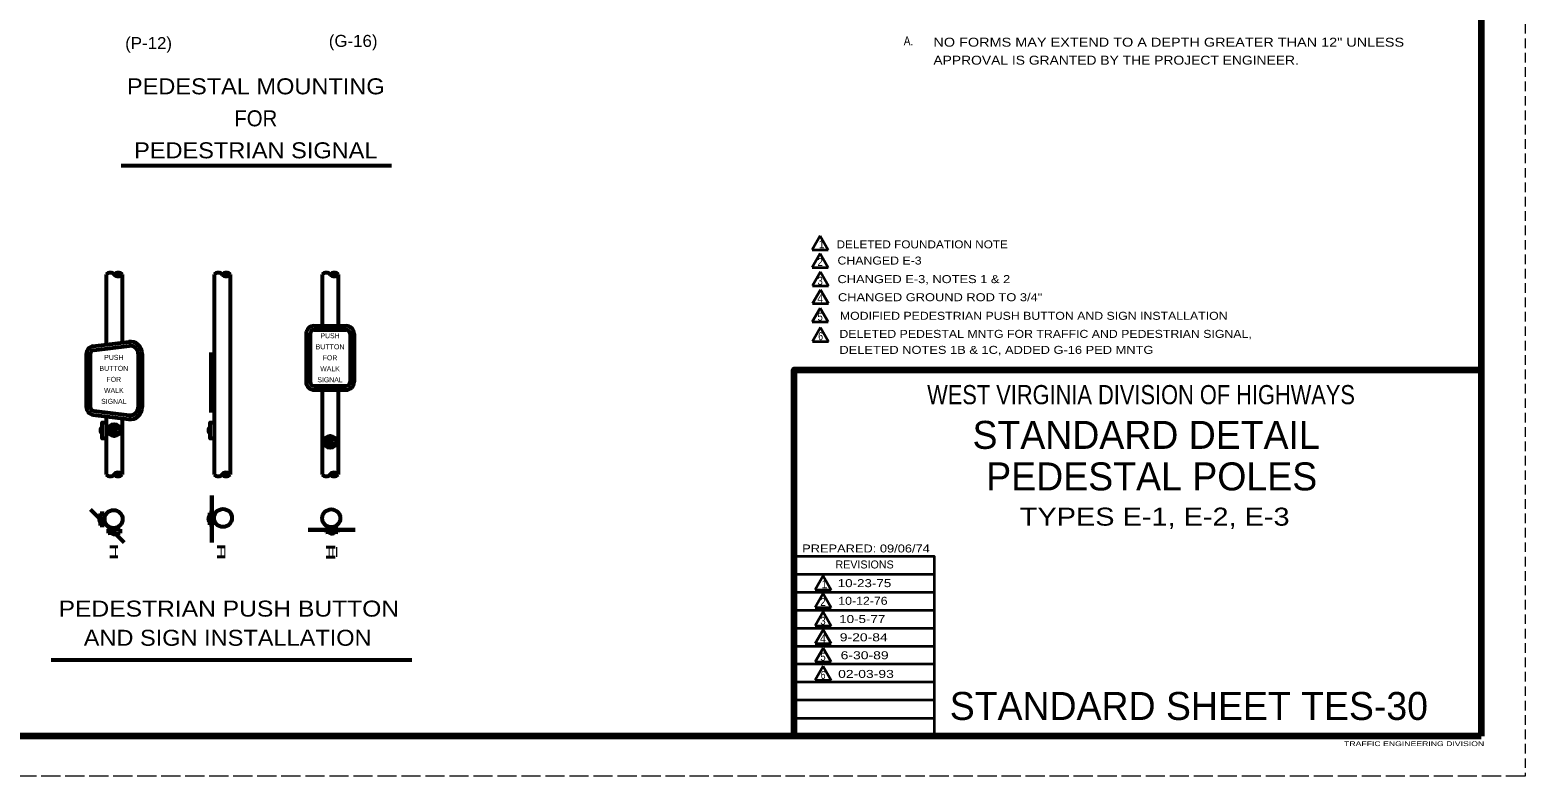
# Model space of a CAD drawing. Extents: x -608 to 72, y 36 to 476.
# Drawn here: x -301.5 to 72.2, y 35.6 to 222.1 of the extents above; entities that cross this region are included whole.
import ezdxf
from ezdxf.enums import TextEntityAlignment as Align

# ---------------------------------------------------------------- set-up
doc = ezdxf.new("R2010")
doc.units = 0
doc.header["$LTSCALE"] = 0.8
doc.linetypes.add('LONG_DASHED', pattern=[7.5, 6, -1.5])
doc.linetypes.add('MEDIUM_DASHED', pattern=[4.5, 3, -1.5])
doc.layers.add('1', color=7, linetype='Continuous', lineweight=53)
doc.layers.add('61', color=7, linetype='Continuous', lineweight=35)

msp = doc.modelspace()

# ---------------------------------------------------------------- linework, layer by layer
at = {"layer": '1', "linetype": 'MEDIUM_DASHED', "lineweight": 13}
msp.add_line((72.1969, 475.5947), (72.1769, 35.5747), dxfattribs=at)
at = {"layer": '1'}
for p, q in [((-278.6894, 188.1896), (-211.1222, 188.1896)), ((-282.3844, 160.9454), (-282.3844, 143.4454)), ((-278.3844, 160.9454), (-278.3844, 143.9454)), ((-251.3844, 160.9454), (-251.3844, 143.9454)), ((-228.3844, 160.9454), (-228.3844, 148.1722)), ((-224.3844, 160.9454), (-224.3844, 148.1192)), ((-232.4268, 146.1192), (-232.4268, 134.1192)), ((-231.4268, 146.1192), (-231.4268, 134.1192)), ((-230.4268, 148.1192), (-222.4268, 148.1192)), ((-230.4268, 147.1192), (-222.4268, 147.1192)), ((-221.4268, 146.1192), (-221.4268, 134.1192)), ((-220.4268, 146.1192), (-220.4268, 134.1192)), ((-285.6325, 143.0394), (-276.7565, 144.1489)), ((-285.5084, 142.0472), (-276.6325, 143.1567)), ((-251.3844, 143.9454), (-251.3844, 110.9958)), ((-287.3844, 141.0548), (-287.3844, 127.8864)), ((-286.3844, 141.0549), (-286.3844, 127.8863)), ((-274.3844, 141.1721), (-274.3844, 127.7692)), ((-273.3844, 141.1721), (-273.3844, 127.7692)), ((-256.1344, 126.4958), (-256.1344, 141.4958)), ((-256.1344, 139.0958), (-255.3844, 139.0958)), ((-256.1344, 137.9958), (-255.3844, 137.9958)), ((-230.4268, 133.1192), (-222.4268, 133.1192)), ((-230.4268, 132.1192), (-222.4268, 132.1192)), ((-228.3844, 132.1192), (-228.3844, 110.9958)), ((-224.3844, 132.1192), (-224.3844, 110.9958)), ((-256.1344, 129.9958), (-255.3844, 129.9958)), ((-256.1344, 128.8958), (-255.3844, 128.8958)), ((-285.6325, 125.9018), (-276.7565, 124.7923)), ((-285.5084, 126.8941), (-276.6325, 125.7846)), ((-282.3844, 125.4958), (-282.3844, 110.9958)), ((-278.3844, 124.9958), (-278.3844, 110.9958)), ((-282.8841, 101.2534), (-283.8841, 101.2534)), ((-255.597, 101.3492), (-256.597, 101.3492)), ((-282.8841, 98.2534), (-283.8841, 98.2534)), ((-282.7841, 99.7534), (-283.7841, 99.7534)), ((-281.8974, 97.3155), (-281.8974, 96.3155)), ((-280.3974, 97.4156), (-280.3974, 96.4155)), ((-278.8974, 97.3155), (-278.8974, 96.3155)), ((-255.597, 98.3492), (-256.597, 98.3492)), ((-255.497, 99.8492), (-256.497, 99.8492)), ((-227.5146, 97.507), (-227.5146, 96.507)), ((-226.0146, 97.6071), (-226.0146, 96.607)), ((-224.5146, 97.507), (-224.5146, 96.507)), ((-296.1583, 64.6672), (-205.9782, 64.6672))]:
    msp.add_line(p, q, dxfattribs=at)
at = {"layer": '1', "lineweight": 35}
for p, q in [((-103.9602, 170.6178), (-105.9602, 167.1537)), ((-103.9602, 170.6178), (-101.9602, 167.1537)), ((-105.9602, 167.1537), (-101.9602, 167.1537)), ((-103.9602, 166.2022), (-105.9602, 162.7382)), ((-103.9602, 166.2022), (-101.9602, 162.7382)), ((-105.9602, 162.7382), (-101.9602, 162.7382)), ((-103.8866, 161.6396), (-105.8866, 158.1755)), ((-103.8866, 161.6396), (-101.8866, 158.1755)), ((-105.8866, 158.1755), (-101.8866, 158.1755)), ((-103.8866, 157.1505), (-105.8866, 153.6864)), ((-103.8866, 157.1505), (-101.8866, 153.6864)), ((-105.8866, 153.6864), (-101.8866, 153.6864)), ((-103.9602, 152.5877), (-105.9602, 149.1237)), ((-103.9602, 152.5877), (-101.9602, 149.1237)), ((-105.9602, 149.1237), (-101.9602, 149.1237)), ((-103.8497, 147.724), (-105.8497, 144.2599)), ((-103.8497, 147.724), (-101.8497, 144.2599)), ((-105.8497, 144.2599), (-101.8497, 144.2599)), ((-75.4231, 85.9947), (-110.4031, 85.9947)), ((-103.2573, 85.6079), (-105.2573, 82.1438)), ((-103.2573, 85.6079), (-101.2573, 82.1438)), ((-75.4231, 81.4947), (-110.4031, 81.4947)), ((-105.2573, 82.1438), (-101.2573, 82.1438)), ((-103.2573, 81.1924), (-105.2573, 77.7283)), ((-103.2573, 81.1924), (-101.2573, 77.7283)), ((-75.4231, 76.9947), (-110.4031, 76.9947)), ((-105.2573, 77.7283), (-101.2573, 77.7283)), ((-103.1838, 76.6298), (-105.1838, 73.1657)), ((-103.1838, 76.6298), (-101.1838, 73.1657)), ((-75.4231, 72.4747), (-110.4031, 72.4747)), ((-105.1838, 73.1657), (-101.1838, 73.1657)), ((-103.1838, 72.1407), (-105.1838, 68.6766)), ((-103.1838, 72.1407), (-101.1838, 68.6766)), ((-75.4231, 67.9947), (-110.4031, 67.9947)), ((-103.2573, 67.5779), (-105.2573, 64.1138)), ((-105.1838, 68.6766), (-101.1838, 68.6766)), ((-103.2573, 67.5779), (-101.2573, 64.1138)), ((-105.2573, 64.1138), (-101.2573, 64.1138)), ((-75.4231, 63.5147), (-110.4031, 63.5147)), ((-103.2239, 63.0232), (-105.2239, 59.5591)), ((-103.2239, 63.0232), (-101.2239, 59.5591)), ((-75.4231, 59.0147), (-110.4031, 59.0147)), ((-105.2239, 59.5591), (-101.2239, 59.5591)), ((-75.4231, 54.5147), (-110.4031, 54.5147)), ((-75.4231, 49.9947), (-110.4031, 49.9947))]:
    msp.add_line(p, q, dxfattribs=at)
at = {"layer": '1', "lineweight": 60}
for p, q in [((-255.9803, 105.7435), (-255.9803, 93.9646)), ((-286.2768, 102.2103), (-277.9047, 93.9587)), ((-231.9415, 97.1089), (-220.1626, 97.1088))]:
    msp.add_line(p, q, dxfattribs=at)
at = {"layer": '1', "lineweight": 40}
for p, q in [((-281.4969, 92.8757), (-279.4969, 92.8757)), ((-281.4969, 90.3757), (-279.4969, 90.3757)), ((-254.6945, 92.8569), (-252.6945, 92.8569)), ((-254.6945, 90.3569), (-252.6945, 90.3569)), ((-227.3913, 92.81), (-225.1913, 92.81)), ((-227.3913, 90.31), (-225.1913, 90.31))]:
    msp.add_line(p, q, dxfattribs=at)
at = {"layer": '1'}
for points in [[(-255.3844, 160.9454), (-255.3844, 143.4454), (-255.3844, 110.9958)], [(-282.3844, 119.9958), (-283.3844, 119.9958), (-283.3844, 123.9958), (-282.3844, 123.9958)], [(-255.3844, 119.9958), (-256.3844, 119.9958), (-256.3844, 123.9958), (-255.3844, 123.9958)], [(-283.8841, 101.2534), (-283.7841, 99.7534), (-283.8841, 98.2534)], [(-282.8841, 101.2534), (-282.7841, 99.7534), (-282.8841, 98.2534)], [(-256.597, 101.3492), (-256.497, 99.8492), (-256.597, 98.3492)], [(-255.597, 101.3492), (-255.497, 99.8492), (-255.597, 98.3492)], [(-281.8974, 97.3155), (-280.3974, 97.4156), (-278.8974, 97.3155)], [(-227.5146, 97.507), (-226.0146, 97.6071), (-224.5146, 97.507)], [(-281.8974, 96.3155), (-280.3974, 96.4155), (-278.8974, 96.3155)], [(-227.5146, 96.507), (-226.0146, 96.607), (-224.5146, 96.507)]]:
    msp.add_lwpolyline(points, dxfattribs=at)
at = {"layer": '1', "lineweight": 158}
msp.add_lwpolyline([(-110.4231, 45.5547), (-110.4231, 137.1347), (61.2369, 137.1347)], dxfattribs=at)
at = {"layer": '1', "lineweight": 35}
msp.add_lwpolyline([(-75.4231, 45.5147), (-75.4231, 90.4747), (-110.4031, 90.4747)], dxfattribs=at)
at = {"layer": '1'}
for centre, radius in [((-280.3915, 122.0646), 1.5), ((-280.3915, 122.0646), 0.75), ((-280.3915, 122.0646), 0.25), ((-280.3997, 122.0652), 0.2098), ((-280.4063, 122.0685), 0.164), ((-280.4096, 122.0685), 0.1278), ((-280.4128, 122.0751), 0.0917), ((-280.4194, 122.0816), 0.0528), ((-280.4194, 122.0817), 0.0197), ((-226.4268, 119.1192), 1.5), ((-226.4268, 119.1192), 0.75), ((-226.4268, 119.1192), 0.25), ((-226.4351, 119.1199), 0.2098), ((-226.4417, 119.1232), 0.164), ((-226.445, 119.1232), 0.1278), ((-226.4482, 119.1298), 0.0917), ((-226.4547, 119.1363), 0.0528), ((-226.4547, 119.1363), 0.0197), ((-280.5435, 99.8226), 2.25), ((-253.2081, 100.0978), 2.25), ((-226.1607, 100.0141), 2.25)]:
    msp.add_circle(centre, radius, dxfattribs=at)
for centre, radius, start, end in [((-281.3844, 160.0295), 1.3561, 42.48748, 137.51252), ((-279.4041, 161.8953), 1.3561, 222.48748, 317.51252), ((-279.3951, 160.0458), 1.3561, 42.48748, 137.51252), ((-254.3844, 160.0295), 1.3561, 42.48748, 137.51252), ((-252.4041, 161.8953), 1.3561, 222.48748, 317.51252), ((-252.3951, 160.0458), 1.3561, 42.48748, 137.51252), ((-227.3844, 160.0295), 1.3561, 42.48748, 137.51252), ((-225.4041, 161.8953), 1.3561, 222.48748, 317.51252), ((-225.3951, 160.0458), 1.3561, 42.48748, 137.51252), ((-230.4268, 146.1192), 2, 90, 180), ((-230.4268, 146.1192), 1, 90, 180), ((-222.4268, 146.1192), 2, 0, 90), ((-222.4268, 146.1192), 1, 0, 90), ((-285.3844, 141.0549), 2, 97.12478, 180), ((-285.3844, 141.0549), 1, 97.12502, 180), ((-276.3844, 141.1721), 3, 0, 97.12484), ((-276.3844, 141.1721), 2, 0, 97.12508), ((-230.4268, 134.1192), 2, 180, 270), ((-230.4268, 134.1192), 1, 180, 270), ((-222.4268, 134.1192), 2, 270, 0), ((-222.4268, 134.1192), 1, 270, 0), ((-285.3844, 127.8864), 2, 180, 262.87522), ((-285.3844, 127.8864), 1, 180, 262.87498), ((-276.3844, 127.7692), 3, 262.87516, 0), ((-276.3844, 127.7691), 2, 262.87492, 0), ((-282.9459, 121.9958), 0.8688, 120.31709, 239.68291), ((-255.9459, 121.9958), 0.8688, 120.31709, 239.68291), ((-281.3844, 111.9118), 1.3561, 222.48748, 317.51252), ((-279.4419, 111.8768), 1.3561, 222.48748, 317.51252), ((-279.4228, 110.0833), 1.3561, 42.48748, 137.51252), ((-254.3844, 111.9118), 1.3561, 222.48748, 317.51252), ((-252.4419, 111.8768), 1.3561, 222.48748, 317.51252), ((-252.4228, 110.0833), 1.3561, 42.48748, 137.51252), ((-227.3844, 111.9118), 1.3561, 222.48748, 317.51252), ((-225.4419, 111.8768), 1.3561, 222.48748, 317.51252), ((-225.4228, 110.0833), 1.3561, 42.48748, 137.51252), ((-283.1525, 99.7534), 1.0134, 132.26342, 227.73658), ((-255.8654, 99.8492), 1.0134, 132.26342, 227.73658), ((-280.3974, 97.0471), 1.0134, 222.26342, 317.73658), ((-226.0146, 97.2386), 1.0134, 222.26342, 317.73658)]:
    msp.add_arc(centre, radius, start, end, dxfattribs=at)
at = {"layer": '61', "lineweight": 158}
for p, q in [((61.2169, 465.5947), (61.2369, 45.5547)), ((61.2369, 45.5547), (-577.8231, 45.5747))]:
    msp.add_line(p, q, dxfattribs=at)
at = {"layer": '61', "linetype": 'LONG_DASHED', "lineweight": 13}
msp.add_line((72.1769, 35.5747), (-607.8831, 35.5547), dxfattribs=at)

# ---------------------------------------------------------------- texts
at = {"layer": '1'}
for s, height, width, p in [('(P-12)', 3, 1.05, (-271.798, 217.3239)), ('(G-16)', 3, 1.05, (-220.6732, 217.8786)), ('PEDESTAL MOUNTING', 4, 1.1, (-245.0061, 206.0188)), ('FOR', 4, 0.95, (-245.0061, 198.0188)), ('PEDESTRIAN SIGNAL', 4, 1.1, (-245.0061, 190.0188)), ('2', 2, 0.9, (-103.9639, 163.1012)), ('3', 2, 0.9, (-103.9639, 158.3912)), ('4', 2, 0.95, (-103.9639, 153.9758)), ('5', 2, 0.9, (-103.9639, 149.4131)), ('6', 2, 0.8, (-103.8534, 144.5493)), ('BUTTON', 1.25, 1.05, (-226.4549, 142.2732)), ('FOR', 1.25, 0.95, (-226.4549, 139.5232)), ('BUTTON', 1.25, 1.05, (-280.4884, 136.8779)), ('FOR', 1.25, 0.95, (-280.4884, 134.1279)), ('WEST VIRGINIA DIVISION OF HIGHWAYS', 4.795, 0.85, (-23.7748, 128.5347)), ('TYPES E-1, E-2, E-3', 4.5, 1.2, (-20.3706, 98.1737)), ('PEDESTRIAN PUSH BUTTON', 4, 1.15, (-251.7355, 75.4311)), ('2', 2, 0.9, (-103.2611, 78.0913)), ('3', 2, 0.9, (-103.2611, 73.3814)), ('AND SIGN INSTALLATION', 4, 1.1, (-252.0357, 68.1401)), ('4', 2, 0.95, (-103.2611, 68.9659)), ('5', 2, 0.9, (-103.2611, 64.4032)), ('6', 2, 0.8, (-103.2276, 59.8485)), ('02-03-93', 2, 1.3, (-92.5164, 60.1012))]:
    msp.add_text(s, height=height, dxfattribs=dict(at, width=width)).set_placement(p, align=Align.CENTER)
for s, height, width, p in [('A.', 2.25, 0.85, (-83.0915, 218.2497)), ('NO FORMS MAY EXTEND TO A DEPTH GREATER THAN 12" UNLESS', 2.25, 1.2, (-75.6697, 217.927)), ('APPROVAL IS GRANTED BY THE PROJECT ENGINEER.', 2.25, 1.15, (-75.6697, 213.427)), ('DELETED FOUNDATION NOTE', 2, 1.1, (-99.8752, 167.5087)), ('CHANGED E-3', 2, 1.15, (-99.637, 163.4592)), ('CHANGED E-3, NOTES 1 & 2', 2, 1.2, (-99.6369, 158.8142)), ('CHANGED GROUND ROD TO 3/4"', 2, 1.2, (-99.5179, 154.2883)), ('MODIFIED PEDESTRIAN PUSH BUTTON AND SIGN INSTALLATION', 2, 1.15, (-99.0414, 149.6432)), ('DELETED PEDESTAL MNTG FOR TRAFFIC AND PEDESTRIAN SIGNAL,', 2, 1.15, (-99.1519, 145.1215)), ('DELETED NOTES 1B & 1C, ADDED G-16 PED MNTG', 2, 1.2, (-99.1519, 141.1215)), ('PREPARED: 09/06/74', 1.998, 1.2, (-108.4631, 91.4747)), ('10-23-75', 2, 1.25, (-99.5815, 82.8012)), ('10-12-76', 2, 1.15, (-99.4342, 78.3857)), ('10-5-77', 2, 1.25, (-99.2135, 73.823)), ('9-20-84', 2, 1.3, (-99.0663, 69.2603)), ('6-30-89', 2, 1.3, (-98.8456, 64.7712)), ('TRAFFIC ENGINEERING DIVISION', 1.2, 1.35, (26.9569, 43.0547))]:
    msp.add_text(s, height=height, dxfattribs=dict(at, width=width)).set_placement(p)
for s, height, p in [('1', 2, (-104.3318, 167.5469)), ('REVISIONS', 1.998, (-100.1431, 87.4747)), ('1', 2, (-103.629, 82.5371)), ('STANDARD SHEET TES-30', 6.993, (-71.5831, 49.5947))]:
    msp.add_text(s, height=height, dxfattribs=at).set_placement(p)
for s, height, p in [('PUSH', 1.25, (-226.4549, 145.0232)), ('PUSH', 1.25, (-280.4884, 139.6279)), ('SIGNAL', 1.25, (-226.4549, 134.0232)), ('WALK', 1.25, (-226.4549, 136.7732)), ('WALK', 1.25, (-280.4884, 131.3779)), ('SIGNAL', 1.25, (-280.4884, 128.6279)), ('STANDARD DETAIL', 6.993, (-22.5061, 117.3747)), ('PEDESTAL POLES', 7, (-21.115, 106.9916)), ('I', 2.5, (-280.0551, 90.385)), ('II', 2.5, (-253.1986, 90.3132)), ('III', 2.5, (-225.7486, 90.3134))]:
    msp.add_text(s, height=height, dxfattribs=at).set_placement(p, align=Align.CENTER)

doc.saveas('drawing.dxf')
